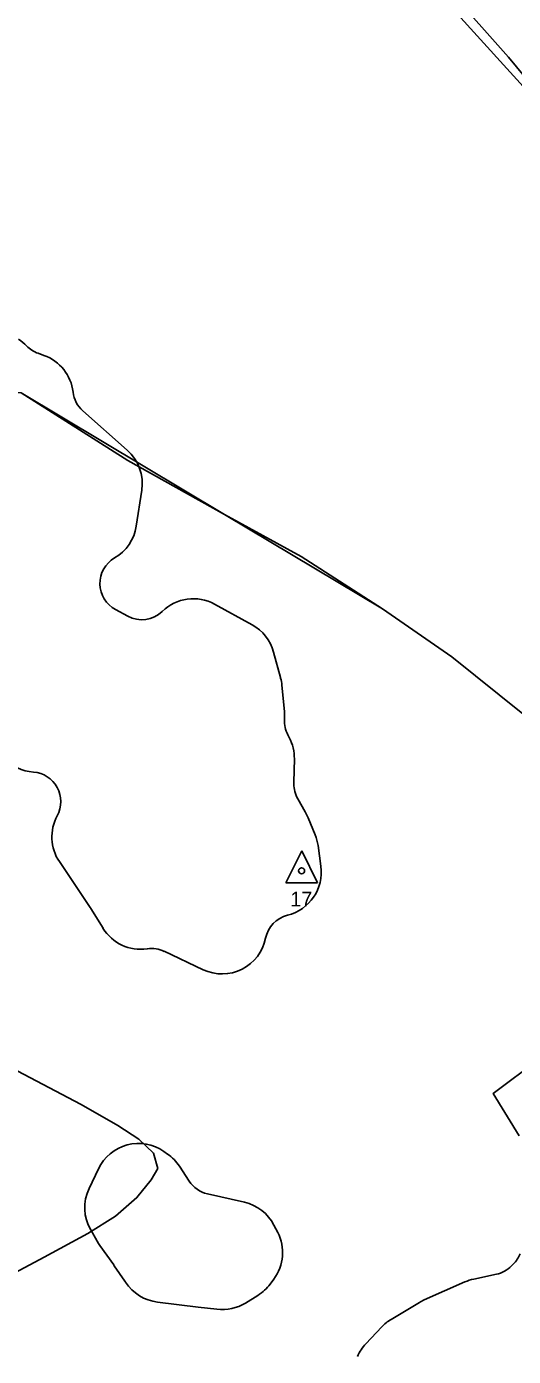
# Model space of a CAD drawing. Extents: x -445049 to -430649, y -1142304 to -1129816.
# Drawn here: x -442451 to -442122, y -1132297 to -1131398 of the extents above; entities that cross this region are included whole.
import ezdxf

# ---------------------------------------------------------------- set-up
doc = ezdxf.new("R2010")
doc.units = 0
for name, color, linetype in [('Vrstva 10', 7, 'Continuous'), ('Vrstva 23', 7, 'Continuous'), ('Vrstva 25', 7, 'Continuous'), ('Vrstva 51', 7, 'Continuous'), ('Vrstva 9', 7, 'Continuous')]:
    doc.layers.add(name, color=color, linetype=linetype)

msp = doc.modelspace()

# ---------------------------------------------------------------- linework, layer by layer
at = {"layer": 'Vrstva 10'}
for points in [[(-442165.52, -1131373.73), (-442125.54, -1131418.84), (-442086.58, -1131466), (-442028.14, -1131529.57), (-441955.35, -1131599.28), (-441812.85, -1131715.13), (-441682.64, -1131817.65), (-441670.34, -1131823.81), (-441625.23, -1131835.08), (-441590.37, -1131835.08), (-441488.87, -1131838.16), (-441456.07, -1131837.13), (-441443.76, -1131840.21), (-441404.81, -1131875.07), (-441364.82, -1131924.28), (-441352.52, -1131968.36), (-441339.19, -1131983.74), (-441305.36, -1132012.45), (-441280.75, -1132028.85), (-441257.17, -1132043.21), (-441226.42, -1132061.66), (-441186.43, -1132080.11)], [(-442115.87, -1131862.97), (-442163.8, -1131824.39), (-442210.77, -1131791.96), (-442317.46, -1131728.12), (-442455.14, -1131645.73), (-442495.49, -1131643.36), (-442604.47, -1131647.64), (-442737.78, -1131568.14), (-442817.2, -1131526.93), (-442857.84, -1131497.77), (-442912.71, -1131446.28), (-442981.25, -1131388.3)], [(-442118.21, -1132148.37), (-442135.82, -1132119.6), (-442104.5, -1132096.23)]]:
    msp.add_lwpolyline(points, dxfattribs=at)
at = {"layer": 'Vrstva 23'}
for p, q in [((-442439.66, -1131620.5), (-442443.66, -1131619.07)), ((-442383.28, -1131684.64), (-442413.36, -1131657.98)), ((-442377.2, -1131735.96), (-442373.51, -1131711.57)), ((-442383.04, -1131796.85), (-442391.33, -1131792.39)), ((-442298.91, -1131802.64), (-442324.27, -1131788.75)), ((-442279.74, -1131838.27), (-442284.36, -1131821.14)), ((-442279.63, -1131838.68), (-442279.71, -1131838.36)), ((-442277.06, -1131861.35), (-442278.75, -1131843.58)), ((-442277.02, -1131861.82), (-442277.06, -1131861.42)), ((-442273.73, -1131878.96), (-442274.69, -1131877.12)), ((-442270.61, -1131909.01), (-442270.32, -1131893.42)), ((-442270.63, -1131910.14), (-442270.61, -1131909.01)), ((-442263.05, -1131929.11), (-442268, -1131920.42)), ((-442262.76, -1131929.61), (-442263.03, -1131929.14)), ((-442256.29, -1131944.67), (-442261.03, -1131933.13)), ((-442252.41, -1131965.89), (-442254.32, -1131952.01)), ((-442429.23, -1131962.85), (-442408.43, -1131993.86)), ((-442408.03, -1131994.48), (-442399.72, -1132007.91)), ((-442369.94, -1132021.83), (-442369.69, -1132021.79)), ((-442358.31, -1132023.5), (-442331.99, -1132035.91)), ((-442356.06, -1132160.57), (-442358.58, -1132158.82)), ((-442402.77, -1132170.57), (-442409.15, -1132183.97)), ((-442341.44, -1132178.94), (-442348.05, -1132168.81)), ((-442304.14, -1132193.17), (-442329.11, -1132187.51)), ((-442408.06, -1132211.84), (-442403.58, -1132219.61)), ((-442281.6, -1132213.54), (-442284.11, -1132208.68)), ((-442401.86, -1132222.34), (-442392.49, -1132235.57)), ((-442122.21, -1132234.94), (-442123.64, -1132236.39)), ((-442392.35, -1132235.76), (-442392.11, -1132236.12)), ((-442392.07, -1132236.17), (-442384.85, -1132246.57)), ((-442133.68, -1132241.87), (-442149.05, -1132245.15)), ((-442286.65, -1132248.5), (-442284.18, -1132245.18)), ((-442154.94, -1132247.05), (-442182.5, -1132259.25)), ((-442362.77, -1132260.77), (-442335.36, -1132264.06)), ((-442303.4, -1132261.34), (-442294.99, -1132256.15)), ((-442185.79, -1132260.96), (-442204.91, -1132272.43)), ((-442335.36, -1132264.06), (-442322.73, -1132265.58)), ((-442211.28, -1132277.55), (-442221.99, -1132288.88))]:
    msp.add_line(p, q, dxfattribs=at)
for centre, radius, start, end in [((-442473.09, -1131634.75), 30, 43.65422, 57.05175), ((-442436.91, -1131600.24), 20, 223.65422, 250.29952), ((-442449.77, -1131648.74), 30, 6.58912, 70.29952), ((-442400.1, -1131643.01), 20, 186.58912, 228.45413), ((-442403.18, -1131707.09), 30, 351.41249, 48.45413), ((-442406.86, -1131731.48), 30, 300.00406, 351.41249), ((-442381.86, -1131774.78), 20, 120.00406, 241.72617), ((-442338.68, -1131815.06), 30, 61.28451, 134.23923), ((-442373.56, -1131779.24), 20, 241.72617, 314.23923), ((-442313.32, -1131828.95), 30, 15.10525, 61.28451), ((-442308.7, -1131846.09), 30, 14.93142, 15.10525), ((-442308.61, -1131846.41), 30, 5.41252, 14.93142), ((-442257.15, -1131859.47), 20, 185.41252, 185.5948), ((-442306.88, -1131864.74), 30, 356.42777, 5.5948), ((-442256.97, -1131867.86), 20, 176.42777, 207.61052), ((-442300.32, -1131892.87), 30, 358.93763, 27.61052), ((-442444.48, -1131872.39), 30, 222.58143, 265.68776), ((-442448.24, -1131922.25), 20, 331.45872, 85.68776), ((-442250.63, -1131910.51), 20, 178.94435, 209.71482), ((-442250.61, -1131909.38), 20, 178.93763, 178.94435), ((-442245.68, -1131919.19), 20, 209.71482, 209.83793), ((-442404.32, -1131946.14), 30, 151.45872, 213.85714), ((-442288.78, -1131944.54), 30, 22.34792, 29.83793), ((-442284.04, -1131956.08), 30, 7.79932, 22.34792), ((-442282.14, -1131969.96), 30, 283.87002, 7.79932), ((-442425.04, -1132005), 20, 31.73644, 33.85714), ((-442270.15, -1132018.51), 20, 103.87002, 168.78139), ((-442374.21, -1131992.13), 30, 211.73644, 278.16841), ((-442319.2, -1132008.78), 30, 244.74891, 348.78139), ((-442366.84, -1132041.59), 20, 64.74891, 98.16841), ((-442375.68, -1132183.46), 30, 55.23551, 154.54444), ((-442373.17, -1132185.21), 30, 33.1373, 55.23551), ((-442324.69, -1132168.01), 20, 213.1373, 257.22711), ((-442382.06, -1132196.87), 30, 154.54444, 209.95361), ((-442310.77, -1132222.43), 30, 27.27847, 77.22711), ((-442308.27, -1132227.29), 30, 323.39541, 27.27847), ((-442420.91, -1132229.6), 20, 29.47589, 29.95372), ((-442377.38, -1132205), 30, 209.47589, 215.31075), ((-442136.41, -1132220.86), 20, 315.25623, 339.03972), ((-442408.81, -1132247.13), 20, 34.62716, 35.31075), ((-442367.42, -1132219.07), 30, 214.62716, 214.75146), ((-442137.85, -1132222.31), 20, 282.03352, 315.25623), ((-442401.29, -1132257.97), 20, 32.6656, 34.75146), ((-442359.2, -1132230.98), 30, 212.6656, 263.14741), ((-442310.73, -1132230.61), 30, 301.65497, 323.39541), ((-442142.8, -1132274.49), 30, 102.03352, 113.87049), ((-442319.14, -1132235.8), 30, 263.14116, 301.65497), ((-442170.36, -1132286.68), 30, 113.87049, 120.96462), ((-442337.75, -1132283.92), 20, 83.14116, 83.14741), ((-442189.47, -1132298.15), 30, 120.96462, 136.62933), ((-442200.18, -1132309.49), 30, 136.62933, 156.33647)]:
    msp.add_arc(centre, radius, start, end, dxfattribs=at)
at = {"layer": 'Vrstva 25'}
msp.add_lwpolyline([(-441192.33, -1132083.25), (-441235.07, -1132065.92), (-441354.08, -1131976.62), (-441366.68, -1131950.53), (-441376.35, -1131916.28), (-441414.99, -1131870.18), (-441448.58, -1131837.2), (-441494.37, -1131833.92), (-441618.53, -1131836.49), (-441649.51, -1131832.41), (-441677.69, -1131821.33), (-441696.39, -1131812.27), (-441769.1, -1131756.02), (-441861.1, -1131681.86), (-441968.26, -1131592.54), (-442035.35, -1131527.06), (-442162.19, -1131387.13)], dxfattribs=at)
at = {"layer": 'Vrstva 51'}
for p, q in [((-442276.04, -1131977.15), (-442265.33, -1131955.63)), ((-442254.62, -1131977.15), (-442265.33, -1131955.63)), ((-442276.04, -1131977.15), (-442254.62, -1131977.15))]:
    msp.add_line(p, q, dxfattribs=at)
msp.add_lwpolyline([(-442472.69, -1132247.93), (-442439.61, -1132230.22), (-442409.97, -1132214.31), (-442391.35, -1132202.51), (-442376.81, -1132190), (-442367.24, -1132177.94), (-442362.56, -1132170.46), (-442365.48, -1132159.94), (-442375.49, -1132150.52), (-442389.63, -1132141.22), (-442414.53, -1132126.98), (-442457.77, -1132104.35)], dxfattribs=at)
msp.add_circle((-442265.42, -1131969.05), 2.03, dxfattribs=at)
at = {"layer": 'Vrstva 9'}
for points in [[(-442981.25, -1131388.3), (-442954.27, -1131411.85), (-442912.71, -1131446.28), (-442857.84, -1131497.77), (-442817.2, -1131526.93), (-442737.78, -1131568.14), (-442604.47, -1131647.64), (-442495.49, -1131643.36), (-442455.14, -1131645.73), (-442382.95, -1131691.5), (-442317.46, -1131728.12), (-442265.69, -1131756.54), (-442210.77, -1131791.96), (-442163.8, -1131824.39), (-442115.87, -1131862.97)], [(-442104.5, -1132096.23), (-442135.82, -1132119.6), (-442118.21, -1132148.37)]]:
    msp.add_lwpolyline(points, dxfattribs=at)

# ---------------------------------------------------------------- texts
at = {"layer": 'Vrstva 51'}
msp.add_text('17', height=10, dxfattribs=at).set_placement((-442273.07, -1131993.16))

doc.saveas('drawing.dxf')
